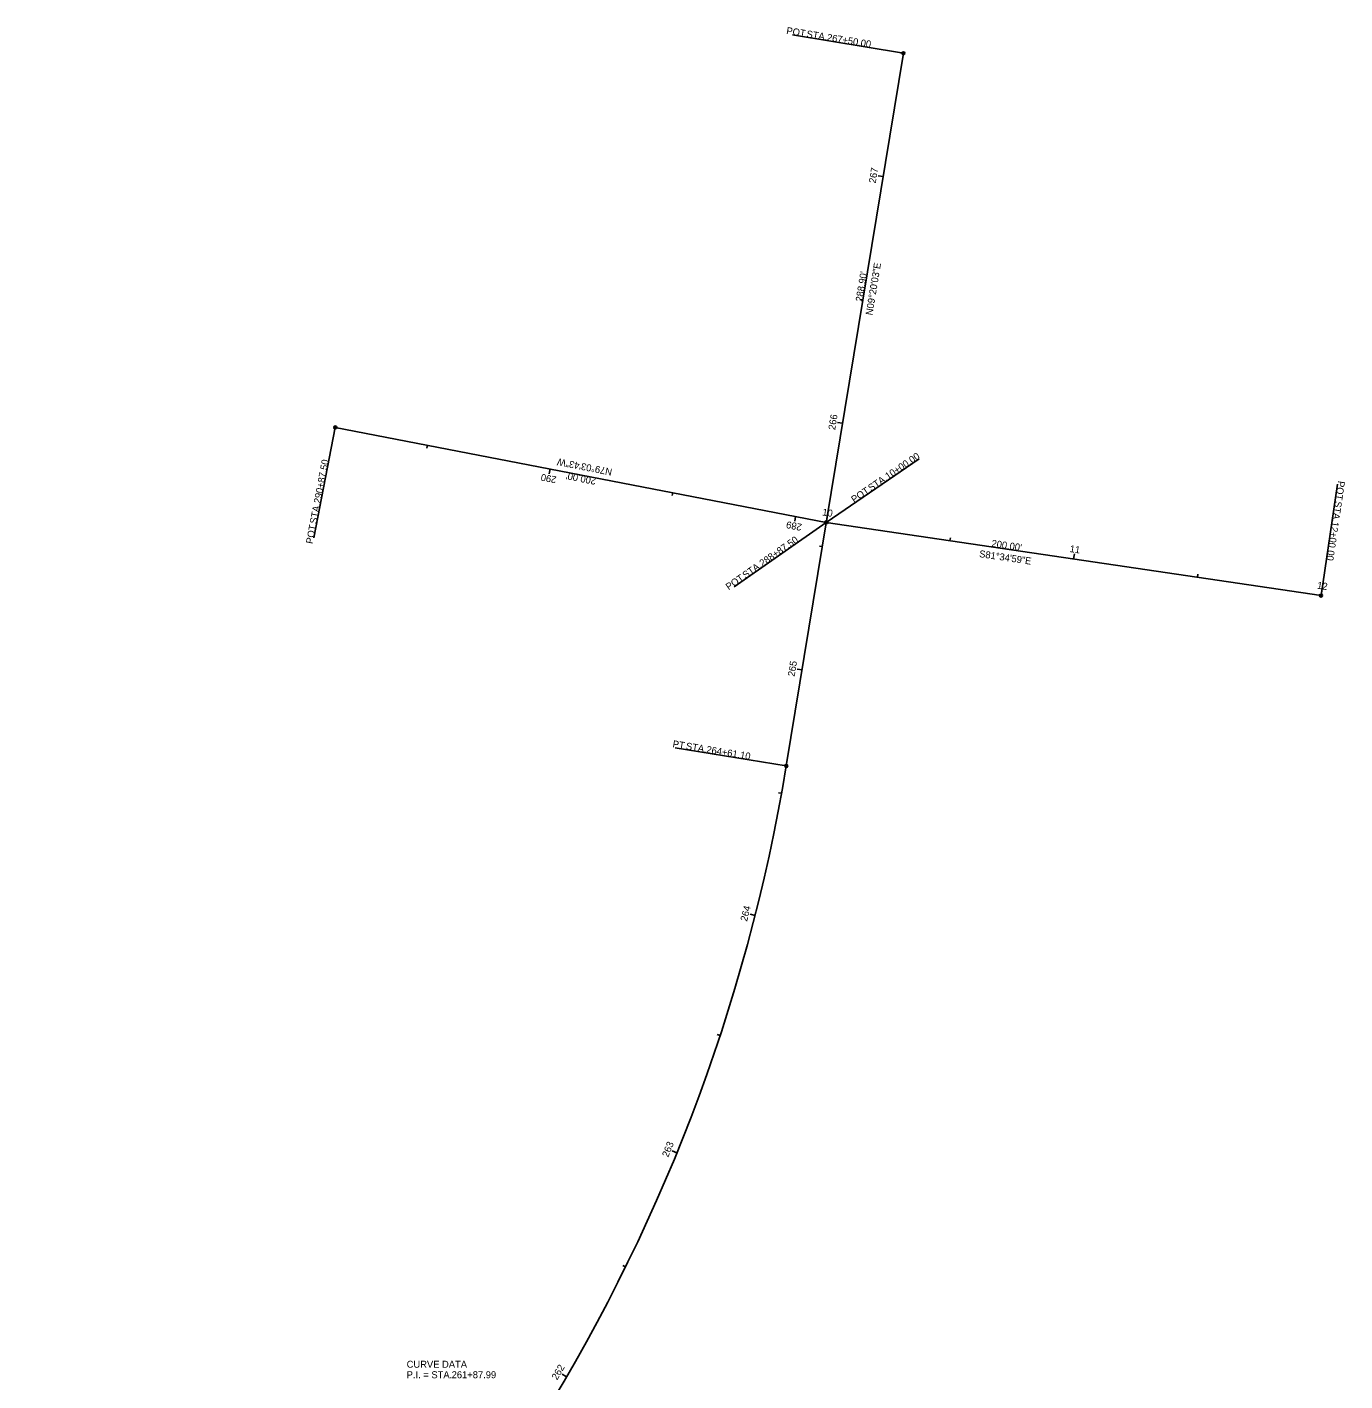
# Model space of a CAD drawing. Extents: x 1481464 to 1482480, y 364592 to 365678.
# Drawn here: x 1481953 to 1482480, y 365137 to 365678 of the extents above; entities that cross this region are included whole.
import ezdxf

# ---------------------------------------------------------------- set-up
doc = ezdxf.new("R2010")
doc.units = 0
for name, color, linetype in [('RD_X_Cells', 7, 'Continuous'), ('SG_X_Poles', 7, 'Continuous'), ('SN_X_Public', 7, 'Continuous'), ('SV_X_Shot_Marker', 7, 'Continuous'), ('UT_X_Electric_Cells', 7, 'Continuous'), ('UT_X_Telecom_Cells', 7, 'Continuous')]:
    doc.layers.add(name, color=color, linetype=linetype)

msp = doc.modelspace()

# ---------------------------------------------------------------- linework, layer by layer
at = {"layer": 'SN_X_Public'}
for p, q in [((1482303.1, 365667.88), (1482258.7, 365675.18)), ((1482075.9, 365518.19), (1482067.36, 365474.01)), ((1482272.26, 365480.24), (1482309.4, 365505.66)), ((1482470.11, 365450.97), (1482476.7, 365495.48)), ((1482272.26, 365480.24), (1482235.4, 365454.43)), ((1482256.25, 365382.8), (1482211.84, 365390.1))]:
    msp.add_line(p, q, dxfattribs=at)
for centre in [(1482303.1, 365667.88), (1482075.9, 365518.19), (1482272.26, 365480.24), (1482272.26, 365480.24), (1482470.11, 365450.97), (1482256.25, 365382.8)]:
    msp.add_circle(centre, 0.6, dxfattribs=at)
at = {"layer": 'SV_X_Shot_Marker'}
for p, q in [((1482256.25, 365382.8), (1482303.1, 365667.88)), ((1482272.26, 365480.24), (1482075.9, 365518.19)), ((1482272.26, 365480.24), (1482470.11, 365450.97))]:
    msp.add_line(p, q, dxfattribs=at)
msp.add_arc((1481549.53, 365498.96), 716.2, 304.25163, 350.66585, dxfattribs=at)
msp.add_arc((1481549.53, 365498.96), 716.2, 304.25163, 350.66585, dxfattribs=at)
at = {"layer": 'UT_X_Electric_Cells'}
for p, q in [((1482303.1, 365667.88), (1482301.92, 365668.07)), ((1482294.99, 365618.54), (1482293.02, 365618.86)), ((1482286.88, 365569.2), (1482285.7, 365569.4)), ((1482278.77, 365519.86), (1482276.8, 365520.19)), ((1482112.71, 365511.08), (1482112.49, 365509.9)), ((1482161.81, 365501.59), (1482161.43, 365499.63)), ((1482210.9, 365492.1), (1482210.67, 365490.93)), ((1482259.99, 365482.62), (1482259.61, 365480.65)), ((1482272.26, 365480.24), (1482272.56, 365482.22)), ((1482321.72, 365472.93), (1482321.9, 365474.11)), ((1482270.67, 365470.52), (1482269.48, 365470.72)), ((1482371.19, 365465.61), (1482371.48, 365467.59)), ((1482420.65, 365458.29), (1482420.82, 365459.48)), ((1482470.11, 365450.97), (1482470.4, 365452.95)), ((1482262.56, 365421.19), (1482260.58, 365421.51)), ((1482254.36, 365371.86), (1482253.18, 365372.08)), ((1482243.78, 365323.01), (1482241.84, 365323.5)), ((1482229.81, 365275.01), (1482228.67, 365275.38)), ((1482212.53, 365228.1), (1482210.68, 365228.85)), ((1482192.02, 365182.51), (1482190.95, 365183.04)), ((1482168.38, 365138.46), (1482166.66, 365139.47))]:
    msp.add_line(p, q, dxfattribs=at)

# ---------------------------------------------------------------- texts
at = {"layer": 'RD_X_Cells'}
for s, rotation, p in [('N09°20\'03"E', 80.6659, (1482290.72, 365562.93)), ('N79°03\'43"W', 169.062, (1482186.8, 365501.65)), ('S81°34\'59"E', 351.5831, (1482333.26, 365466.37))]:
    msp.add_text(s, height=2.8, rotation=rotation, dxfattribs=at).set_placement(p)
at = {"layer": 'SG_X_Poles'}
for s, p in [('CURVE DATA', (1482104.44, 365142.09)), ('P.I. = STA. ', (1482104.44, 365137.89)), ('261+87.99', (1482122.43, 365137.89))]:
    msp.add_text(s, height=2.8, dxfattribs=at).set_placement(p)
at = {"layer": 'SN_X_Public'}
for s, rotation, p in [('POT', 350.6659, (1482256.14, 365675.63)), (' STA. ', 350.6659, (1482263.17, 365674.48)), ('267+50.00', 350.6659, (1482272.37, 365672.96)), ('290+87.50', 79.062, (1482069.95, 365487.62)), ('10+00.00', 34.3868, (1482296.97, 365497.2)), ('POT', 34.3868, (1482283.4, 365487.91)), (' STA. ', 34.3868, (1482289.28, 365491.93)), ('POT', 261.5831, (1482476.95, 365496.95)), (' STA. ', 261.5831, (1482475.91, 365489.89)), (' STA. ', 79.062, (1482068.18, 365478.46)), ('POT', 79.062, (1482066.83, 365471.46)), ('12+00.00', 261.5831, (1482474.54, 365480.67)), ('288+87.50', 34.9992, (1482246.73, 365462.41)), (' STA. ', 34.9992, (1482239.09, 365457.06)), ('POT', 34.9992, (1482233.25, 365452.97)), ('PT', 350.6659, (1482210.65, 365390.33)), (' STA. ', 350.6659, (1482214.95, 365389.63)), ('264+61.10', 350.6659, (1482224.14, 365388.12))]:
    msp.add_text(s, height=2.8, rotation=rotation, dxfattribs=at).set_placement(p)
at = {"layer": 'UT_X_Electric_Cells'}
for s, rotation, p in [('267', 80.6659, (1482292, 365615.74)), ('266', 80.6659, (1482275.78, 365517.06)), ('290', 169.062, (1482164.54, 365498.52)), ('10', 351.5831, (1482270.5, 365483.03)), ('289', 169.062, (1482262.68, 365479.55)), ('11', 351.5831, (1482369.47, 365468.39)), ('12', 351.5831, (1482468.4, 365453.75)), ('265', 80.6659, (1482259.57, 365418.43)), ('264', 75.7779, (1482240.55, 365320.44)), ('263', 67.7779, (1482209.01, 365226.08)), ('262', 59.7779, (1482164.61, 365136.95))]:
    msp.add_text(s, height=2.8, rotation=rotation, dxfattribs=at).set_placement(p)
at = {"layer": 'UT_X_Telecom_Cells'}
for s, rotation, p in [("288.90'", 80.6659, (1482286.7, 365568.33)), ("200.00'", 169.062, (1482180.39, 365497.96)), ("200.00'", 351.5831, (1482338.19, 365470.53))]:
    msp.add_text(s, height=2.8, rotation=rotation, dxfattribs=at).set_placement(p)

doc.saveas('drawing.dxf')
